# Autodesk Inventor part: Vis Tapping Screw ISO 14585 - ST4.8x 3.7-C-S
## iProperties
Created: 2011-01
Part Number: Vis Tapping Screw ISO 14585 - ST4.8x 3.7-C-S
Document SubType Name: Modeling
Designer: eric
Density: 1 g/cm^3
Mass: 0.442621 g
Surface Area: 4.98801 cm^2
Volume: 0.442621 cm^3
Author: eric
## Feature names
1. Base1
